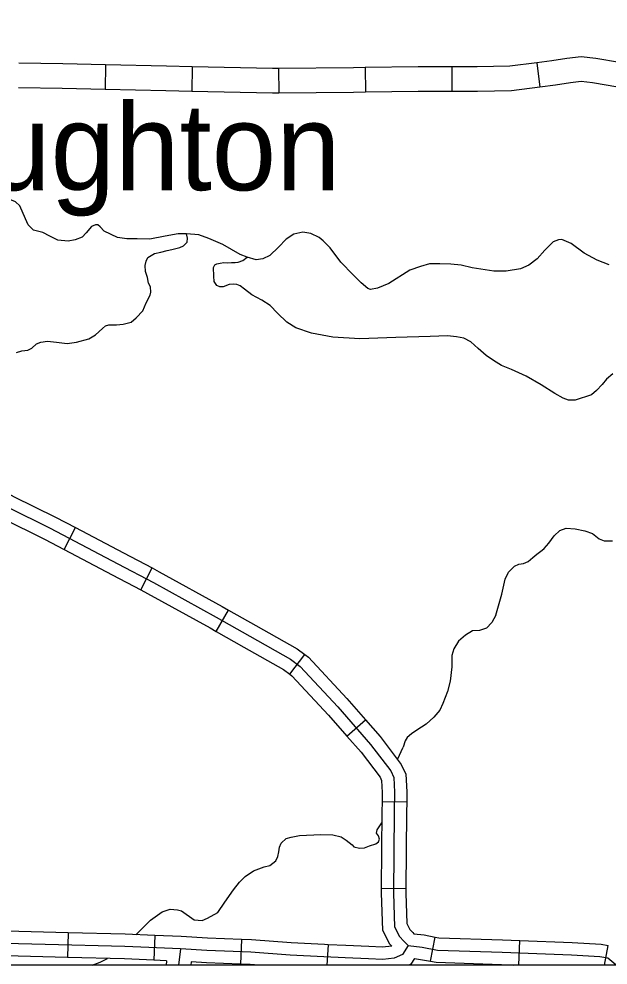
# Model space of a CAD drawing. Extents: x 8749 to 11879, y 13275 to 15339.
# Drawn here: x 10210.7 to 10282.5, y 13439.9 to 13555.1 of the extents above; entities that cross this region are included whole.
import ezdxf

# ---------------------------------------------------------------- set-up
doc = ezdxf.new("R2010")
doc.units = 0
for name, color, linetype in [('Level 24', 7, 'Continuous'), ('Level 32', 7, 'Continuous'), ('Level 35', 7, 'Continuous'), ('Level 45', 7, 'Continuous'), ('R_Draft', 7, 'Continuous')]:
    doc.layers.add(name, color=color, linetype=linetype)

msp = doc.modelspace()

# ---------------------------------------------------------------- linework, layer by layer
at = {"layer": 'Level 32'}
for p, q in [((10221.27, 13549.46), (10221.2, 13546.46)), ((10231.82, 13549.23), (10231.76, 13546.23)), ((10242.33, 13549.02), (10242.36, 13546.02)), ((10252.89, 13549.13), (10252.92, 13546.13)), ((10263.47, 13549.21), (10263.47, 13546.21)), ((10273.81, 13549.71), (10274.19, 13546.74)), ((10216.2, 13490.46), (10217.6, 13493.12)), ((10225.56, 13485.55), (10226.95, 13488.21)), ((10234.76, 13480.48), (10236.24, 13483.09)), ((10243.71, 13475.29), (10245.53, 13477.68)), ((10250.66, 13467.75), (10252.92, 13469.73)), ((10254.96, 13459.79), (10257.96, 13459.73)), ((10254.84, 13449.22), (10257.84, 13449.19)), ((10216.7, 13443.79), (10216.62, 13440.79)), ((10227.27, 13443.46), (10227.15, 13440.46)), ((10260.87, 13440.33), (10261.41, 13443.28)), ((10237.81, 13442.99), (10237.71, 13439.99)), ((10248.38, 13442.35), (10248.24, 13439.87)), ((10271.63, 13439.87), (10271.74, 13442.84)), ((10282.05, 13439.87), (10282.5, 13442.25))]:
    msp.add_line(p, q, dxfattribs=at)
for points in [[(10284.44, 13549.78), (10283.89, 13549.77), (10281.01, 13550.23), (10279.2, 13550.44), (10277.49, 13550.23), (10275.65, 13549.95), (10273.81, 13549.71)], [(10221.27, 13549.46), (10216.04, 13549.58), (10210.7, 13549.68)], [(10231.82, 13549.23), (10228.68, 13549.3), (10221.27, 13549.46)], [(10242.33, 13549.02), (10241.62, 13549.02), (10231.82, 13549.23)], [(10252.89, 13549.13), (10251.46, 13549.11), (10242.33, 13549.02)], [(10263.47, 13549.21), (10259.34, 13549.21), (10252.89, 13549.13)], [(10273.81, 13549.71), (10270.51, 13549.3), (10266.55, 13549.21), (10263.47, 13549.21)], [(10274.19, 13546.74), (10270.74, 13546.3), (10266.59, 13546.21), (10263.47, 13546.21)], [(10284.48, 13546.78), (10283.67, 13546.77), (10280.6, 13547.26), (10279.21, 13547.42), (10277.9, 13547.26), (10276.07, 13546.98), (10274.19, 13546.74)], [(10221.2, 13546.46), (10215.98, 13546.58), (10210.65, 13546.68)], [(10231.76, 13546.23), (10228.61, 13546.3), (10221.2, 13546.46)], [(10242.36, 13546.02), (10241.61, 13546.02), (10231.76, 13546.23)], [(10252.92, 13546.13), (10251.49, 13546.11), (10242.36, 13546.02)], [(10263.47, 13546.21), (10259.36, 13546.21), (10252.92, 13546.13)], [(10208.42, 13497.86), (10208.44, 13497.84), (10210.06, 13496.93), (10215.18, 13494.39), (10217.6, 13493.12)], [(10206.64, 13495.44), (10206.81, 13495.32), (10208.66, 13494.28), (10213.82, 13491.72), (10216.2, 13490.46)], [(10217.6, 13493.12), (10223.45, 13490.04), (10226.95, 13488.21)], [(10216.2, 13490.46), (10222.06, 13487.38), (10225.56, 13485.55)], [(10226.95, 13488.21), (10227.8, 13487.76), (10235.47, 13483.53), (10236.24, 13483.09)], [(10225.56, 13485.55), (10226.38, 13485.12), (10234, 13480.91), (10234.76, 13480.48)], [(10236.24, 13483.09), (10239.57, 13481.21), (10244.62, 13478.37), (10245.53, 13477.68)], [(10234.76, 13480.48), (10238.1, 13478.59), (10242.96, 13475.86), (10243.71, 13475.29)], [(10245.53, 13477.68), (10245.98, 13477.34), (10250.66, 13472.31), (10252.92, 13469.73)], [(10243.71, 13475.29), (10243.96, 13475.1), (10248.43, 13470.3), (10250.66, 13467.75)], [(10252.92, 13469.73), (10254.72, 13467.68), (10257.3, 13464.3), (10257.87, 13463.09), (10257.98, 13460.95), (10257.96, 13459.73)], [(10250.66, 13467.75), (10252.39, 13465.78), (10254.72, 13462.73), (10254.9, 13462.34), (10254.98, 13460.89), (10254.96, 13459.79)], [(10254.96, 13459.79), (10254.93, 13458.47), (10254.84, 13449.22)], [(10257.96, 13459.73), (10257.93, 13458.42), (10257.84, 13449.19)], [(10254.84, 13449.22), (10254.84, 13448.61), (10254.99, 13444.13), (10255.85, 13442.47), (10256.13, 13442.17)], [(10257.84, 13449.19), (10257.84, 13448.64), (10257.97, 13444.91), (10258.33, 13444.2), (10258.69, 13443.82), (10258.83, 13443.68), (10260.08, 13443.53), (10261.41, 13443.28)], [(10258.15, 13442.25), (10257.44, 13441.16), (10256.45, 13440.69), (10255.04, 13440.55), (10253.29, 13440.64), (10250.46, 13440.74), (10247.87, 13440.88), (10243.76, 13441.07), (10238.95, 13441.45), (10233.62, 13441.64), (10230.4, 13441.83), (10223.62, 13442.11), (10204.16, 13442.63), (10188.74, 13443), (10176.42, 13443.16)], [(10216.7, 13443.79), (10206.14, 13444.07)], [(10227.27, 13443.46), (10223.67, 13443.61), (10216.7, 13443.79)], [(10237.81, 13442.99), (10233.69, 13443.13), (10230.48, 13443.33), (10227.27, 13443.46)], [(10261.41, 13443.28), (10261.88, 13443.19), (10269.64, 13442.92), (10271.74, 13442.84)], [(10248.38, 13442.35), (10247.94, 13442.38), (10243.86, 13442.57), (10239.04, 13442.94), (10237.81, 13442.99)], [(10256.13, 13442.17), (10255, 13442.05), (10253.36, 13442.14), (10250.53, 13442.24), (10248.38, 13442.35)], [(10271.74, 13442.84), (10278.11, 13442.6), (10281.66, 13442.41), (10282.5, 13442.25)], [(10216.62, 13440.79), (10206.06, 13441.08)], [(10227.15, 13440.46), (10223.57, 13440.61), (10216.62, 13440.79)], [(10230.4, 13441.83), (10230.14, 13439.87)], [(10228.7, 13440.4), (10227.15, 13440.46)], [(10228.7, 13440.4), (10228.63, 13439.87)], [(10231.71, 13440.25), (10231.66, 13439.87)], [(10237.71, 13439.99), (10233.55, 13440.14), (10231.71, 13440.25)], [(10239.93, 13439.87), (10238.87, 13439.95), (10237.71, 13439.99)], [(10258.9, 13440.65), (10258.47, 13439.99), (10258.2, 13439.87)], [(10258.9, 13440.65), (10259.62, 13440.56), (10260.87, 13440.33)], [(10260.87, 13440.33), (10261.56, 13440.2), (10269.53, 13439.92), (10270.97, 13439.87)]]:
    msp.add_lwpolyline(points, dxfattribs=at)
at = {"layer": 'Level 35'}
for points in [[(10221.08, 13529.21), (10220.59, 13529.75), (10220.32, 13529.97), (10220.05, 13529.99), (10219.54, 13529.8), (10218.9, 13529.02), (10218.41, 13528.48), (10217.57, 13528.16), (10216.71, 13528.02), (10215.44, 13528.13), (10214.47, 13528.59), (10213.61, 13529.05), (10212.49, 13529.32), (10211.82, 13529.97), (10211.52, 13530.72), (10210.8, 13532.32), (10210.28, 13532.8), (10209.41, 13533.15), (10208.46, 13533.41), (10207.51, 13533.58), (10206.64, 13533.67), (10206.16, 13533.71), (10205.64, 13533.75), (10205.13, 13533.64)], [(10237.67, 13526.36), (10235.55, 13527.59), (10233.85, 13528.32), (10232.61, 13528.78), (10231.13, 13528.91), (10230.1, 13528.89), (10228.51, 13528.59), (10226.65, 13528.24), (10225.11, 13528.29), (10223.85, 13528.29), (10222.72, 13528.43), (10221.08, 13529.21)], [(10231.19, 13527.88), (10231.24, 13528.37), (10231.13, 13528.91)], [(10281.16, 13525.67), (10279.58, 13526.55), (10278.01, 13527.71), (10276.85, 13528.22), (10276.45, 13528.17), (10275.8, 13527.93), (10274.78, 13526.9), (10273.86, 13525.85), (10272.86, 13525.09), (10271.84, 13524.63), (10270.09, 13524.34), (10268.58, 13524.34), (10265.93, 13524.77), (10264.59, 13525.07), (10263.35, 13525.2), (10262, 13525.25), (10260.73, 13525.25), (10259.63, 13524.93), (10258.33, 13524.47), (10255.77, 13522.83), (10254.42, 13522.26), (10253.53, 13522.12), (10253.22, 13522.23), (10252.39, 13522.93), (10251.44, 13523.9), (10249.93, 13525.44), (10248.64, 13527.2), (10247.77, 13528.03), (10247.29, 13528.44), (10246.27, 13528.92), (10245.29, 13529.09), (10244.19, 13528.87), (10243.26, 13528.24), (10242.32, 13527.29), (10241.3, 13526.25), (10240.44, 13525.85), (10239.63, 13525.74), (10238.53, 13526.04), (10237.67, 13526.36)], [(10210.43, 13514.43), (10211.05, 13514.64), (10211.8, 13514.73), (10212.29, 13514.97), (10212.83, 13515.51), (10213.39, 13515.72), (10214.2, 13515.81), (10215.28, 13515.72), (10216.6, 13515.54), (10217.73, 13515.72), (10219.24, 13516.1), (10220.05, 13516.61), (10220.89, 13517.37), (10221.24, 13517.69), (10221.67, 13517.8), (10222.59, 13517.8), (10223.42, 13517.91), (10224.37, 13518.13), (10225.01, 13518.67), (10225.82, 13519.5), (10226.23, 13520.5), (10226.71, 13521.42), (10226.79, 13521.81), (10226.74, 13522.43), (10226.49, 13522.89), (10226.39, 13523.57), (10226.14, 13524.32), (10226.09, 13525.05), (10226.2, 13525.56), (10226.41, 13526.02), (10227.22, 13526.48), (10228, 13526.67), (10228.78, 13526.86), (10229.32, 13526.97), (10230.3, 13527.24), (10230.75, 13527.45), (10231.19, 13527.88)], [(10234.82, 13525.25), (10235.23, 13525.33), (10235.67, 13525.39), (10236.13, 13525.37), (10236.62, 13525.39), (10237.05, 13525.39), (10237.42, 13525.46), (10237.99, 13525.65), (10238.53, 13526.04)], [(10260.83, 13516.4), (10256.63, 13516.27), (10252.26, 13516.13), (10248.95, 13516.32), (10246.36, 13516.8), (10244.44, 13517.45), (10243.37, 13518.13), (10242.21, 13519.23), (10241.34, 13520.18), (10240.32, 13520.83), (10239.08, 13521.47), (10238.19, 13522.15), (10237.67, 13522.58), (10237.25, 13522.74), (10236.9, 13522.77), (10236.33, 13522.72), (10235.6, 13522.44), (10235.2, 13522.44), (10234.82, 13522.61), (10234.5, 13523.09), (10234.44, 13523.74), (10234.42, 13524.79), (10234.58, 13525.12), (10234.82, 13525.25)], [(10282.64, 13525.11), (10281.16, 13525.67)], [(10269.5, 13512.87), (10268.54, 13513.46), (10267.63, 13514.08), (10266.68, 13514.94), (10265.77, 13515.73), (10264.93, 13516.18), (10264.01, 13516.37), (10262.91, 13516.48), (10260.83, 13516.4)], [(10283.08, 13511.84), (10282.3, 13511.2), (10281.76, 13510.55), (10281.07, 13509.82), (10280.49, 13509.28), (10278.47, 13508.66), (10277.69, 13508.66), (10277.02, 13508.88), (10276.02, 13509.44), (10274.33, 13510.5), (10272.52, 13511.58), (10270.71, 13512.36), (10269.5, 13512.87)], [(10268.83, 13482.45), (10269.54, 13485.03), (10269.95, 13486.86), (10270.35, 13487.7), (10271.08, 13488.43), (10271.62, 13488.67), (10272.18, 13488.75), (10272.75, 13488.99), (10273.34, 13489.5), (10273.8, 13489.91), (10274.45, 13490.4), (10274.72, 13490.58), (10275.28, 13491.23), (10275.93, 13492.12), (10276.63, 13492.77), (10277.41, 13493.04), (10278.49, 13492.99), (10279.68, 13492.74), (10280.6, 13492.39), (10281.43, 13491.77), (10282.02, 13491.53), (10283.02, 13491.53)], [(10268.83, 13482.45), (10268.32, 13481.59), (10267.67, 13480.89), (10266.83, 13480.62), (10265.97, 13480.54), (10265.13, 13480.05), (10264.27, 13479.32), (10263.71, 13478.35), (10263.46, 13477.57), (10263.44, 13476.17), (10263.27, 13474.44), (10262.92, 13473.17), (10262.38, 13471.71), (10262.01, 13470.9), (10261.28, 13470.04), (10260.31, 13469.18), (10259.2, 13468.48), (10258.53, 13468.02), (10258.02, 13467.59), (10257.77, 13467.15), (10257.53, 13466.4)], [(10256.84, 13464.9), (10257.53, 13466.4)], [(10230.52, 13446.48), (10232.07, 13445.38), (10233.02, 13445.3), (10233.67, 13445.57), (10234.93, 13446.27), (10235.8, 13447.52), (10236.85, 13449.03), (10237.58, 13449.95), (10238.28, 13450.67), (10239.3, 13451.32), (10240.57, 13451.81), (10241.3, 13452), (10242, 13452.56), (10242.27, 13453.08), (10242.38, 13453.67), (10242.46, 13454.24), (10242.65, 13454.72), (10243.29, 13455.26), (10243.89, 13455.43), (10244.88, 13455.64), (10247.5, 13455.78), (10248.96, 13455.72), (10249.98, 13455.48), (10250.6, 13455.07), (10251.3, 13454.51), (10251.52, 13454.26), (10252.22, 13454.08), (10252.81, 13454.13), (10253.43, 13454.4), (10254.19, 13454.64), (10254.51, 13454.89), (10254.65, 13455.18), (10254.51, 13455.59), (10254.29, 13455.94), (10254.35, 13456.34), (10254.92, 13457.18)], [(10224.96, 13443.55), (10226.74, 13445.34), (10228.17, 13446.34), (10229.12, 13446.67), (10230.03, 13446.59), (10230.52, 13446.48)], [(10219.62, 13439.87), (10220.59, 13440.21), (10221.51, 13440.66)]]:
    msp.add_lwpolyline(points, dxfattribs=at)
at = {"layer": 'Level 45'}
for points in [[(10207.62, 13496.58), (10209.36, 13495.6), (10214.5, 13493.05), (10222.75, 13488.71), (10227.09, 13486.44), (10234.73, 13482.22), (10238.84, 13479.9), (10243.79, 13477.12), (10244.97, 13476.22), (10249.55, 13471.31), (10253.55, 13466.73), (10256.01, 13463.52), (10256.38, 13462.71), (10256.48, 13460.92), (10256.43, 13458.45), (10256.34, 13448.62), (10256.48, 13444.52), (10257.09, 13443.34), (10257.61, 13442.77), (10258.15, 13442.25)], [(10258.15, 13442.25), (10259.85, 13442.04), (10261.72, 13441.7), (10269.59, 13441.42), (10278.04, 13441.11), (10281.48, 13440.92), (10282.47, 13440.73), (10283.44, 13439.95), (10283.51, 13439.87)]]:
    msp.add_lwpolyline(points, dxfattribs=at)
at = {"layer": 'R_Draft'}
msp.add_lwpolyline([(9678.09, 14456.3), (10959.72, 14456.3), (10959.72, 13439.87), (9678.09, 13439.87)], close=True, dxfattribs=at)

# ---------------------------------------------------------------- texts
at = {"layer": 'Level 24'}
msp.add_text('Boughton', height=10.56, dxfattribs=at).set_placement((10189.44, 13534.2))

doc.saveas('drawing.dxf')
